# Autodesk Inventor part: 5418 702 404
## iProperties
Created: 2008-06
Part Number: 5418 702 404
Material: Stahl
Document SubType Name: Modeling
Designer: Goedde
Mass: 69.1689 g
Surface Area: 35.3641 cm^2
Volume: 8.81132 cm^3
Density: 7.85 g/cm^3
Author: Goedde
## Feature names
1. Extrusion1
2. Rundung1 [Fillet]
3. Fase1 [Chamfer]
4. Bohrung1 [Hole]
